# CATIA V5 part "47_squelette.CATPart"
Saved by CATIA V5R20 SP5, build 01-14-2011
Part number: 47_squelette
Publications: "Plan yz", "Plan.1"
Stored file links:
  C:\Documents and Settings\anizard\Bureau\13\47_squelette.CATPart
  C:\Documents and Settings\anizard\Bureau\13\anizard.CATProduct
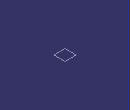
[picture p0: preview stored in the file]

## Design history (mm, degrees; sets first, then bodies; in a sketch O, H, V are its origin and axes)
Parameters
  epaisseur = 8 mm
Set1
  Plane1: linked copy from another document
Body1 (main body)
  Plane2: type Offset, RefPlane Plane1, Offset 8, reversed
